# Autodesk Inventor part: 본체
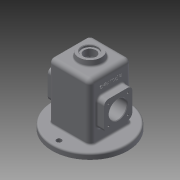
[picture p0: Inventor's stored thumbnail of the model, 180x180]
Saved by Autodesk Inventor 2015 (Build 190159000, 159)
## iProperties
Created: 2021-08
Part Number: 본체
Material: 일반
Document SubType Name: Modeling
Designer: 1054878
Density: 1 g/cm^3
Appearance: 기본값
Author: 1054878
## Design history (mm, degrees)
sketch "스케치1"
  geometry: C1 r 67 at (0, 0); 1 further point
  constraints: 1 centre point, 1 coincident
  dimensions: "d0" = 134 diameter of C1
extrude "돌출1" new body sketch "스케치1" distance "d1" = 10; taper "d2" = 0 deg
sketch "스케치2"
  geometry: L1 (-37, 37)-(37, 37); L2 (37, 37)-(37, -37); L3 (37, -37)-(-37, -37); L4 (-37, -37)-(-37, 37); L5 (-37, 37)-(37, -37); L6 (37, 37)-(-37, -37); C1 r 67 at (0, 0) reference
  constraints: 12 end point, 2 midpoint, 2 parallel, 1 horizontal, 1 perpendicular
  dimensions: "d3" = 74 distance of L1.start L1.end; "d4" = 74 distance of L1.end L2.end
extrude "돌출2" join sketch "스케치2" distance "d5" = 100; taper "d6" = 0 deg
feature "쉘1" dims "d7" = 5
sketch "스케치3"
  geometry: L1 (-32, 32)-(-32, -32) reference; L2 (32, 32)-(-32, 32) reference; L3 (32, -32)-(32, 32) reference; L4 (-32, -32)-(32, -32) reference; C1 r 62 at (0, 0) reference
extrude "돌출3" join sketch "스케치3" stored distance "d8" = 10; taper "d9" = 0 deg
sketch "스케치4"
  geometry: L1 (0, 0)-(0, 55); C1 r 67 at (0, 0) reference
  constraints: 2 end point, 1 vertical
  dimensions: "d11" = 55 distance of L1.start L1.end
hole "구멍1" sketch "스케치4" at (0, 55) diameter "d12" = 9; stored, may be unused: countersink angle "d16" = 90 deg, drill point angle "d18" = 118 deg; dims "d13" = 6, "d14" = 4, "d15" = 2, "d17" = 8
sketch "스케치5"
  geometry: L1 (-100, 0)-(-100, 74) reference; L2 (10, -30)-(10, 104) reference; L3 (-20, 62)-(-70, 62); L4 (-70, 62)-(-70, 12); L5 (-70, 12)-(-20, 12); L6 (-20, 12)-(-20, 62); L7 (-20, 62)-(-70, 12); L8 (-70, 62)-(-20, 12); 4 further points
  constraints: 12 end point, 4 midpoint, 2 parallel, 1 horizontal, 1 horizontal alignment, 1 perpendicular
  dimensions: "d76" = 50 distance of L3.end L4.end; "d77" = 50 distance of L3.start L3.end; "d78" = 55 distance from line of L2 point (-45, 37)
extrude "돌출4" join sketch "스케치5" distance "d24" = 13; taper "d26" = 0 deg; dims "d25" = 12, "d27" = 0
node "작업 평면1"
sketch "스케치17"
  geometry: C1 r 20 at (0, 0); 1 further point
  constraints: 1 centre point, 1 coincident
  dimensions: "d99" = 40 diameter of C1
extrude "돌출11" join sketch "스케치17" stored distance "d100" = 7; taper "d101" = 6 deg
fillet "모깎기1" dims "d42" = 8
fillet "모깎기2" dims "d43" = 8
fillet "모깎기5" dims "d59" = 3
fillet "모깎기6" dims "d60" = 3
fillet "모깎기7" dims "d61" = 3
fillet "모깎기8" dims "d62" = 3
sketch "스케치12"
  geometry: L1 (0, -8)-(89, -8) reference; L2 (-18, 9)-(-18, 49) reference; 2 further points
  constraints: 1 other
  dimensions: "d97" = 37 distance from line of L1 point (10, 29); "d102" = 28 distance from line of point (10, 29) L2
feature "엠보싱1" sketch "스케치12" dims "d65" = 0.5, "d66" = 0
sketch "스케치13"
  geometry: L1 (0, 58)-(0, 0) reference; C1 r 25 at (-55, 29); 2 further points
  constraints: 1 centre point, 1 horizontal alignment, 1 midpoint
  dimensions: "d67" = 50 diameter of C1; "d68" = 55 distance of point (0, 29) C1.centre
extrude "돌출8" join sketch "스케치13" distance "d69" = 7; taper "d70" = -20 deg
sketch "스케치15"
  geometry: L1 (-70, 62)-(-70, 12) reference; L2 (10, -30)-(10, 104) reference; C1 r 16 at (-45, 37); 2 further points
  constraints: 1 centre point, 1 horizontal alignment, 1 midpoint
  dimensions: "d79" = 32 diameter of C1; "d80" = 55 distance from line of L2 C1.centre
extrude "돌출10" cut sketch "스케치15" stored distance "d81" = 7; taper "d82" = 0 deg
fillet "모깎기11" dims "d83" = 8
sketch "스케치16"
  geometry: A1 r 8 centre (-62, 54) between (-62, 62) and (-70, 54) reference; A2 r 8 centre (-62, 20) between (-70, 20) and (-62, 12) reference; A3 r 8 centre (-28, 20) between (-28, 12) and (-20, 20) reference; A4 r 8 centre (-28, 54) between (-20, 54) and (-28, 62) reference; 1 further point
hole "구멍4" sketch "스케치16" at (-62, 54), (-28, 54), (-62, 20), (-28, 20) diameter "d84" = 3.242; stored, may be unused: countersink angle "d88" = 90 deg, drill point angle "d90" = 118 deg; dims "d85" = 8, "d86" = 28, "d87" = 4, "d89" = 10
fillet "모깎기12" dims "d91" = 3
chamfer "모따기2" distance "d92" = 1; stored, may be unused: second distance "d93" = 2, angle "d94" = 45 deg
sketch "스케치18"
  geometry: C1 r 20 at (0, 0) reference
hole "구멍5" sketch "스케치18" at (0, 0) diameter "d103" = 21; stored, may be unused: countersink angle "d107" = 90 deg, drill point angle "d109" = 118 deg; dims "d104" = 8, "d105" = 28, "d106" = 4, "d108" = 10
chamfer "모따기3" distance "d110" = 1; stored, may be unused: second distance "d111" = 2, angle "d112" = 45 deg
fillet "모깎기13" dims "d113" = 3
node "솔리드1"
pattern_circular "원형 패턴1" dims angle "d20" = 360 deg
mirror "대칭1"
mirror "대칭4"
mirror "대칭5"
